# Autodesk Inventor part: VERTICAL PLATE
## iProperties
Created: 2004-06
Part Number: VERTICAL PLATE
Document SubType Name: Modeling
Designer: garding
Manufacturer: Standard
Standards Organization: Custom
Material: Steel, Mild
Author: garding
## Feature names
1. Extrusion1
2. Extrusion2
3. Extrusion3
4. Fillet1
5. Extrusion4
6. Extrusion5
7. Rectangular Pattern1
8. Extrusion6
9. Rectangular Pattern2
10. Hole1
11. Rectangular Pattern3
12. Extrusion7
